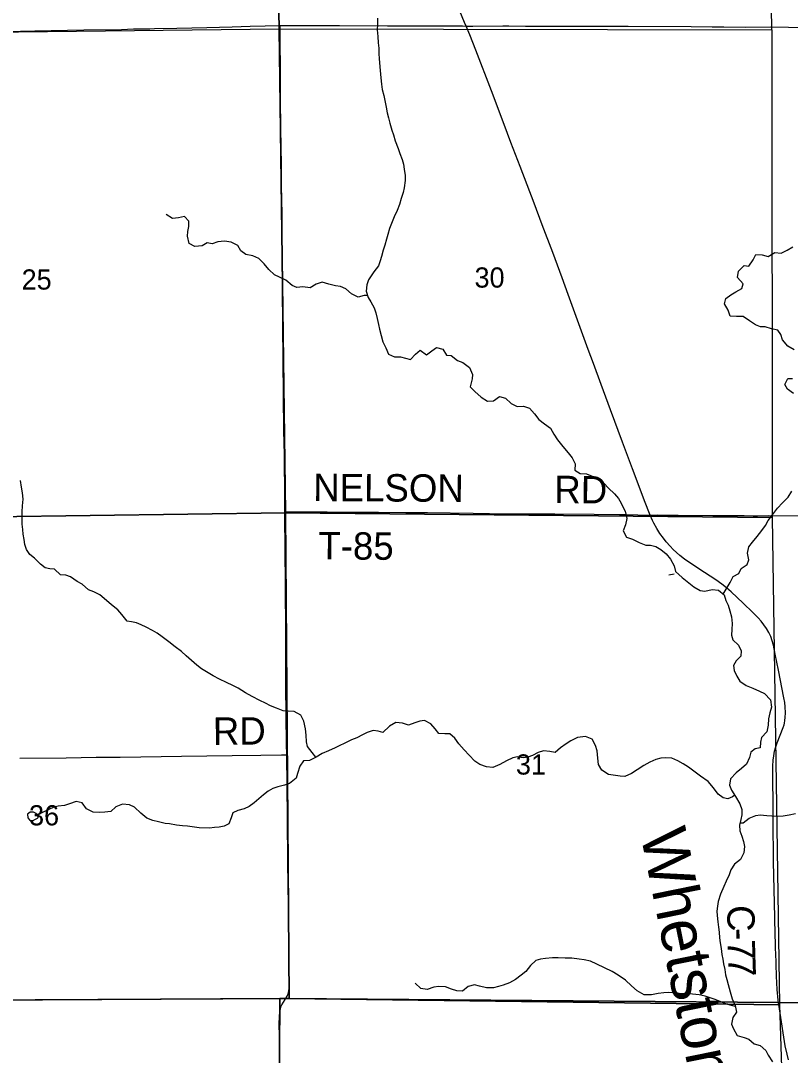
# Model space of a CAD drawing. Extents: x 0 to 70.2, y 0 to 31.4.
# Drawn here: x 4.18 to 5.776, y 18.211 to 20.357 of the extents above; entities that cross this region are included whole.
import ezdxf

# ---------------------------------------------------------------- set-up
doc = ezdxf.new("R2010")
doc.units = 0
for name, color, linetype in [('GM_X_County_Road', 7, 'Continuous'), ('GM_X_County_Road_Text', 7, 'Continuous'), ('GM_X_Minor_Lake', 7, 'Continuous'), ('GM_X_Minor_River', 7, 'Continuous'), ('GM_X_Minor_River_Text', 7, 'Continuous'), ('GM_X_Section', 7, 'Continuous'), ('GM_X_Section_Text', 7, 'Continuous'), ('GM_X_State_Route', 7, 'Continuous'), ('GM_X_Township_Road', 7, 'Continuous'), ('GM_X_Township_Road_Text', 7, 'Continuous')]:
    doc.layers.add(name, color=color, linetype=linetype)

msp = doc.modelspace()

# ---------------------------------------------------------------- linework, layer by layer
at = {"layer": 'GM_X_County_Road'}
for points in [[(5.1036, 20.3455), (5.1003, 20.3533), (5.0907, 20.3762), (5.0746, 20.4168), (5.0732, 20.4206), (5.0703, 20.4283), (5.054, 20.4719), (5.0374, 20.5145), (5.0298, 20.5347), (5.0262, 20.5443)], [(3.6924, 20.3283), (3.7175, 20.3279), (3.7548, 20.3276), (3.7734, 20.3275), (3.8387, 20.3284), (3.9101, 20.3298), (3.9352, 20.3303), (4.0435, 20.3325), (4.1495, 20.3344), (4.209, 20.3357), (4.3109, 20.3376), (4.3888, 20.3388), (4.4136, 20.3397), (4.4478, 20.3401), (4.4571, 20.3406), (4.5037, 20.3416), (4.5658, 20.3429), (4.6186, 20.3442), (4.6559, 20.3455), (4.7179, 20.3465)], [(4.7179, 20.3465), (4.7443, 20.3469), (4.782, 20.3471), (4.8413, 20.3471), (4.9408, 20.346), (5.0429, 20.3458), (5.0742, 20.346), (5.0964, 20.346), (5.1036, 20.3455)], [(5.1036, 20.3455), (5.1179, 20.3452), (5.1801, 20.3461), (5.1925, 20.3459), (5.2267, 20.3457), (5.3195, 20.3451), (5.3748, 20.3452), (5.4401, 20.3451), (5.5706, 20.3444), (5.6141, 20.3443), (5.637, 20.3441), (5.638, 20.3441)], [(5.4857, 19.3314), (5.4844, 19.3344), (5.4753, 19.3575), (5.4488, 19.4271), (5.4281, 19.4824), (5.4031, 19.5494), (5.3839, 19.6019), (5.3677, 19.6455), (5.3571, 19.6747), (5.3157, 19.7886), (5.3027, 19.8235), (5.2833, 19.8759), (5.2616, 19.9337), (5.2446, 19.9783), (5.2156, 20.0547), (5.1967, 20.1041), (5.1823, 20.1418), (5.1561, 20.2116), (5.1241, 20.2959), (5.1114, 20.3276), (5.1036, 20.3455)], [(5.638, 20.3441), (5.6825, 20.3436), (5.7353, 20.3437), (5.7726, 20.3433), (5.8783, 20.343), (5.9498, 20.3425), (5.9848, 20.3424)], [(5.7519, 18.3199), (5.7512, 18.3256), (5.7489, 18.3471), (5.7473, 18.375), (5.746, 18.4246), (5.7457, 18.4291), (5.7458, 18.4326), (5.7446, 18.4716), (5.744, 18.4848), (5.7439, 18.4941), (5.7442, 18.4973), (5.7415, 18.6123), (5.7411, 18.6433), (5.7409, 18.6682), (5.7406, 18.7241), (5.7397, 18.7924), (5.7399, 18.8109), (5.7407, 18.8233), (5.7418, 18.8324), (5.7435, 18.8415), (5.7459, 18.8504), (5.749, 18.8592), (5.7613, 18.8905), (5.7633, 18.8964), (5.764, 18.8995), (5.7651, 18.9056), (5.7658, 18.9118), (5.7662, 18.9212), (5.7657, 18.9337), (5.7646, 18.943), (5.763, 18.9522), (5.7514, 19.0097), (5.745, 19.0432), (5.7412, 19.0615), (5.7388, 19.0706), (5.7355, 19.0794), (5.7315, 19.0879), (5.7268, 19.096), (5.7214, 19.1038), (5.7156, 19.1111), (5.7094, 19.1181), (5.6984, 19.1291), (5.6783, 19.1486), (5.6534, 19.172), (5.644, 19.1802), (5.6342, 19.188), (5.6215, 19.197), (5.5981, 19.2123), (5.5722, 19.2294), (5.5569, 19.24), (5.547, 19.2475), (5.5399, 19.2535), (5.5332, 19.2598), (5.5268, 19.2666), (5.5187, 19.2759), (5.5129, 19.2833), (5.5058, 19.2934), (5.4992, 19.3038), (5.4932, 19.3146), (5.4905, 19.3202), (5.4857, 19.3314)], [(5.7724, 18.2014), (5.7694, 18.2133), (5.7657, 18.2306), (5.7536, 18.3071), (5.7519, 18.3199)]]:
    msp.add_lwpolyline(points, dxfattribs=at)
at = {"layer": 'GM_X_Minor_Lake'}
for points in [[(4.2147, 18.7092), (4.212, 18.7126), (4.206, 18.7149), (4.1995, 18.715), (4.1934, 18.7112), (4.1942, 18.7036), (4.1976, 18.699), (4.2021, 18.6963), (4.2044, 18.6971), (4.2105, 18.7005)], [(4.2105, 18.7005), (4.2145, 18.7028), (4.2158, 18.7041), (4.2158, 18.7052), (4.2147, 18.7092)]]:
    msp.add_lwpolyline(points, dxfattribs=at)
at = {"layer": 'GM_X_Minor_River'}
for points in [[(4.9201, 20.3617), (4.9196, 20.3492), (4.9192, 20.3378), (4.9203, 20.3238), (4.9213, 20.3109), (4.9228, 20.2995), (4.9227, 20.2885), (4.9231, 20.2778), (4.9252, 20.2535), (4.9267, 20.2383), (4.9281, 20.2254), (4.9296, 20.214), (4.9329, 20.2015), (4.9348, 20.1912), (4.9381, 20.1772), (4.94, 20.1658), (4.9426, 20.1555), (4.9452, 20.1445), (4.9493, 20.1297), (4.953, 20.1198), (4.9568, 20.1076), (4.9628, 20.0917), (4.9661, 20.081), (4.971, 20.0692), (4.9736, 20.059), (4.9755, 20.0491), (4.9769, 20.0358), (4.9772, 20.0252), (4.9753, 20.0104), (4.973, 20.0005), (4.9691, 19.9877), (4.9656, 19.9759), (4.9606, 19.9634), (4.9541, 19.9502), (4.9487, 19.9361), (4.9449, 19.9255), (4.941, 19.9134), (4.9387, 19.9035), (4.9349, 19.891), (4.9318, 19.8808), (4.9279, 19.8679), (4.9252, 19.8584), (4.9218, 19.8486), (4.9122, 19.8357), (4.9015, 19.8191), (4.8977, 19.8089), (4.8965, 19.796), (4.9002, 19.783), (4.9058, 19.7735), (4.9126, 19.7613), (4.9163, 19.7511), (4.9193, 19.7393), (4.9219, 19.7264), (4.9242, 19.7169), (4.9275, 19.7036), (4.9312, 19.691), (4.9372, 19.6781), (4.9429, 19.6652), (4.9554, 19.6594), (4.9675, 19.6597), (4.9781, 19.657)], [(4.8991, 19.7867), (4.8922, 19.7865), (4.8797, 19.7831), (4.8661, 19.7904), (4.854, 19.8007), (4.8434, 19.8053), (4.8324, 19.8069), (4.8187, 19.81), (4.8047, 19.8146), (4.7926, 19.8101), (4.78, 19.8026), (4.7652, 19.805), (4.7527, 19.8031), (4.7428, 19.8073), (4.7296, 19.8184), (4.7167, 19.8249), (4.7061, 19.8295), (4.6944, 19.841), (4.685, 19.8528), (4.674, 19.8639), (4.6612, 19.8692), (4.6464, 19.872), (4.6366, 19.8796), (4.6298, 19.8903), (4.6162, 19.8975), (4.6021, 19.8995), (4.5885, 19.8984), (4.5767, 19.8939), (4.5664, 19.8959), (4.5558, 19.8899), (4.541, 19.8884), (4.5293, 19.8945), (4.5255, 19.9101), (4.5263, 19.9196), (4.5283, 19.9302), (4.5283, 19.9409), (4.5197, 19.9508), (4.5067, 19.9478), (4.4946, 19.9467), (4.4817, 19.9551)], [(5.7842, 19.674), (5.7713, 19.6816), (5.76, 19.6946), (5.7566, 19.7056), (5.7506, 19.7151), (5.7373, 19.7178), (5.7241, 19.7221), (5.7142, 19.7221), (5.704, 19.726), (5.6915, 19.734), (5.6786, 19.7435), (5.6646, 19.7432), (5.6517, 19.7437), (5.6472, 19.7562), (5.6397, 19.7692), (5.6428, 19.7809), (5.653, 19.7881), (5.6629, 19.7945), (5.6755, 19.8013), (5.6786, 19.8107), (5.6669, 19.8244), (5.6685, 19.8373), (5.6807, 19.8491), (5.6901, 19.8479), (5.6993, 19.8607), (5.705, 19.8717), (5.7176, 19.8713), (5.7301, 19.8674), (5.7442, 19.8761), (5.757, 19.8749), (5.7696, 19.8809), (5.7814, 19.8877)], [(4.9781, 19.657), (4.9884, 19.6543), (4.9987, 19.6649), (5.0082, 19.6732), (5.0218, 19.6636), (5.0328, 19.6723), (5.0424, 19.6787), (5.0552, 19.6752), (5.0632, 19.6634), (5.0726, 19.6623), (5.0855, 19.6523), (5.0968, 19.6481), (5.1105, 19.6374), (5.1168, 19.6233), (5.116, 19.6138), (5.1118, 19.5975), (5.122, 19.5876), (5.1348, 19.5762), (5.1477, 19.5674), (5.1606, 19.5681), (5.1732, 19.5775), (5.1857, 19.574), (5.1974, 19.5626), (5.2095, 19.5568), (5.2224, 19.5571), (5.2353, 19.5533), (5.2455, 19.5415), (5.2545, 19.5293), (5.2666, 19.5209), (5.2787, 19.5117), (5.2859, 19.4991), (5.293, 19.4873), (5.3043, 19.4736), (5.3153, 19.4607), (5.3239, 19.4504), (5.33, 19.4374), (5.3295, 19.4245), (5.3405, 19.4173), (5.3534, 19.4168), (5.3655, 19.4122), (5.3757, 19.4072), (5.3893, 19.3973), (5.3992, 19.3874), (5.4112, 19.3755), (5.4199, 19.3656), (5.4227, 19.3611)], [(5.783, 19.5836), (5.7705, 19.5928), (5.7648, 19.6023), (5.771, 19.6144), (5.7805, 19.6144)], [(4.7921, 18.8292), (4.7841, 18.8393), (4.7747, 18.8511), (4.7728, 18.8613), (4.7717, 18.875), (4.7707, 18.8879), (4.7673, 18.9042), (4.7609, 18.9164), (4.7473, 18.9237), (4.7344, 18.9249), (4.7238, 18.9257), (4.7102, 18.9307), (4.6977, 18.9361), (4.6878, 18.9415), (4.6757, 18.9468), (4.6598, 18.9549), (4.6458, 18.9625), (4.6307, 18.9721), (4.6197, 18.9778), (4.6068, 18.984), (4.5921, 18.9913), (4.5788, 18.9982), (4.5686, 19.0039), (4.555, 19.0127), (4.5451, 19.0203), (4.5338, 19.0299), (4.5229, 19.0394), (4.513, 19.0482), (4.4998, 19.0581), (4.4869, 19.0685), (4.4733, 19.0792), (4.4627, 19.0864), (4.4529, 19.0918), (4.4397, 19.0987), (4.4294, 19.1037), (4.4196, 19.1079), (4.4097, 19.1098), (4.4003, 19.1114), (4.3897, 19.1255), (4.3814, 19.135), (4.3682, 19.145), (4.3576, 19.1545), (4.344, 19.1659), (4.3311, 19.1721), (4.3205, 19.1763), (4.3069, 19.1878), (4.2971, 19.1935), (4.2831, 19.2031), (4.2732, 19.2069), (4.2622, 19.2077), (4.2498, 19.2195), (4.2399, 19.22), (4.2304, 19.2219), (4.2206, 19.2296), (4.2085, 19.2418), (4.1987, 19.2494), (4.1915, 19.2597), (4.1885, 19.2703), (4.1867, 19.281), (4.1848, 19.292), (4.1838, 19.3015), (4.183, 19.3125), (4.1827, 19.3239), (4.1824, 19.3379), (4.1832, 19.3508), (4.1848, 19.3645), (4.1837, 19.3774), (4.1815, 19.3892), (4.1793, 19.4032)], [(5.6368, 19.1676), (5.6452, 19.1812), (5.6513, 19.1914), (5.6578, 19.2039), (5.6696, 19.2103), (5.6742, 19.2205), (5.6868, 19.2288), (5.6902, 19.2387), (5.6873, 19.2524), (5.6904, 19.2652), (5.6976, 19.2755), (5.7075, 19.2868), (5.7175, 19.2993), (5.7247, 19.3099), (5.7305, 19.3205), (5.7412, 19.3348), (5.7496, 19.3454), (5.7602, 19.3568), (5.7717, 19.3689), (5.7793, 19.3813)], [(5.4227, 19.3611), (5.4335, 19.3398), (5.4372, 19.3242), (5.4341, 19.3113), (5.4295, 19.2984), (5.4362, 19.2858), (5.4491, 19.2816), (5.4624, 19.2743), (5.4764, 19.269), (5.4862, 19.2689), (5.4976, 19.2662), (5.5074, 19.2601), (5.5184, 19.2513), (5.5275, 19.2402), (5.535, 19.2258), (5.538, 19.2144), (5.5516, 19.2022), (5.5621, 19.1938), (5.5761, 19.1827), (5.5894, 19.175), (5.5989, 19.1738), (5.614, 19.1772), (5.6273, 19.1756), (5.6387, 19.1661), (5.6428, 19.1543), (5.6473, 19.1444), (5.651, 19.133), (5.6544, 19.1204), (5.6558, 19.1064), (5.655, 19.0939), (5.6542, 19.0825), (5.6568, 19.0726), (5.6689, 19.0619), (5.6745, 19.0497), (5.6733, 19.0387), (5.6642, 19.0289), (5.6581, 19.0191), (5.6599, 19.0092), (5.6655, 18.9974), (5.6712, 18.9871), (5.6848, 18.9776), (5.6988, 18.9722), (5.7125, 18.966), (5.7227, 18.9611), (5.7348, 18.9481), (5.7373, 18.9329), (5.7339, 18.9215), (5.7311, 18.9086), (5.7303, 18.8957), (5.7272, 18.8817), (5.7165, 18.87), (5.7142, 18.8601), (5.7138, 18.8487), (5.7035, 18.8465), (5.694, 18.8397), (5.6913, 18.8284), (5.6852, 18.8151), (5.6753, 18.806), (5.6642, 18.7966), (5.652, 18.7841), (5.65, 18.7712), (5.6545, 18.7606), (5.6625, 18.748), (5.6715, 18.7328), (5.676, 18.721), (5.6756, 18.71), (5.6736, 18.6998), (5.6709, 18.6884), (5.6716, 18.6766), (5.6757, 18.6656), (5.6791, 18.6542), (5.6809, 18.6439), (5.6801, 18.6306), (5.6732, 18.617), (5.6606, 18.6072), (5.653, 18.5955), (5.6492, 18.5852), (5.6434, 18.572), (5.638, 18.5614), (5.6311, 18.5451), (5.6265, 18.5299), (5.6249, 18.5205), (5.6241, 18.5102), (5.6245, 18.5007), (5.6259, 18.4878), (5.627, 18.4764), (5.6285, 18.4665), (5.6295, 18.4548), (5.631, 18.4445), (5.6325, 18.4324), (5.6343, 18.4198), (5.6362, 18.4103), (5.6376, 18.4004), (5.6402, 18.389), (5.6421, 18.378), (5.6447, 18.3685), (5.6473, 18.3579), (5.6514, 18.3423), (5.6559, 18.3282), (5.6615, 18.3142), (5.6649, 18.3005)], [(5.5353, 19.2091), (5.5243, 19.2068)], [(5.661, 18.7504), (5.656, 18.7473), (5.6465, 18.7428), (5.637, 18.7447), (5.6268, 18.7528), (5.617, 18.7657), (5.6057, 18.7787), (5.5902, 18.7897), (5.5762, 18.8001), (5.5652, 18.8085), (5.5539, 18.8157), (5.5429, 18.8215), (5.5304, 18.8269), (5.5171, 18.8281), (5.5076, 18.827), (5.4974, 18.8244), (5.4848, 18.8191), (5.4723, 18.812), (5.4582, 18.8029), (5.4468, 18.7954), (5.4331, 18.7894), (5.4236, 18.7902), (5.4088, 18.7922), (5.399, 18.7937), (5.385, 18.8021), (5.3782, 18.8143), (5.3767, 18.8272), (5.3757, 18.8424), (5.3723, 18.8538), (5.3652, 18.8668), (5.3511, 18.8722), (5.3348, 18.87), (5.3207, 18.8632), (5.3112, 18.8572), (5.2998, 18.8485), (5.2884, 18.8391), (5.2774, 18.841), (5.2645, 18.8426), (5.2531, 18.8392), (5.2413, 18.8328), (5.2318, 18.8295), (5.2223, 18.828), (5.2105, 18.8299), (5.2003, 18.8277), (5.1874, 18.8217), (5.1737, 18.8138), (5.1592, 18.8078), (5.1459, 18.8094), (5.1323, 18.8144), (5.1217, 18.8213), (5.11, 18.8335), (5.0998, 18.8445), (5.0889, 18.8567), (5.0806, 18.8685), (5.0696, 18.8777), (5.0594, 18.8774), (5.0468, 18.8782), (5.0397, 18.8881), (5.0306, 18.8984), (5.0174, 18.9053), (5.0075, 18.9038), (4.9976, 18.9005), (4.9839, 18.896), (4.9718, 18.8998), (4.9578, 18.9014), (4.9449, 18.8935), (4.9307, 18.8807), (4.9213, 18.883), (4.9107, 18.8849), (4.8985, 18.8808), (4.8886, 18.8759), (4.8768, 18.8695), (4.8662, 18.865), (4.851, 18.8579), (4.8414, 18.8534), (4.8319, 18.8489), (4.8179, 18.8421), (4.8053, 18.8369), (4.7924, 18.8293), (4.7787, 18.8226), (4.7665, 18.8215), (4.7585, 18.8105), (4.7539, 18.7957), (4.7512, 18.7859), (4.7375, 18.7746), (4.7272, 18.7712), (4.7128, 18.7679), (4.7025, 18.7641), (4.693, 18.7585), (4.6831, 18.7509), (4.6736, 18.743), (4.6641, 18.7347), (4.6534, 18.7272), (4.6431, 18.7223), (4.6302, 18.7189), (4.6196, 18.7137), (4.6161, 18.7034), (4.6115, 18.6909), (4.6016, 18.686), (4.5917, 18.6842), (4.5818, 18.6831)], [(4.5818, 18.6831), (4.5716, 18.682), (4.5496, 18.6829), (4.5352, 18.6848), (4.5257, 18.686), (4.5155, 18.6868), (4.5026, 18.6884), (4.4885, 18.6908), (4.4791, 18.6919), (4.4658, 18.695), (4.4537, 18.6978), (4.4416, 18.7028), (4.4291, 18.7135), (4.4155, 18.7257), (4.4056, 18.7306), (4.3905, 18.7315), (4.3768, 18.7262), (4.3669, 18.7164), (4.354, 18.715), (4.3441, 18.7146), (4.3297, 18.7155), (4.3161, 18.722), (4.307, 18.7349), (4.2945, 18.7373), (4.2808, 18.7324), (4.2706, 18.7294), (4.2576, 18.728), (4.2482, 18.7257), (4.2145, 18.7094)], [(5.672, 18.693), (5.6781, 18.6933), (5.6907, 18.7031), (5.7044, 18.7083), (5.7139, 18.7094), (5.7275, 18.7086), (5.7382, 18.7078), (5.748, 18.707), (5.7613, 18.7073), (5.7742, 18.7095), (5.7867, 18.7125)], [(5.662, 18.3122), (5.657, 18.3138), (5.6441, 18.3173), (5.6308, 18.3223), (5.6202, 18.3265), (5.61, 18.33), (5.5994, 18.3334), (5.5869, 18.3365), (5.5736, 18.3381), (5.5633, 18.3386), (5.5497, 18.3386), (5.5376, 18.3402), (5.5243, 18.341), (5.514, 18.3407), (5.5023, 18.3389), (5.4886, 18.3366), (5.473, 18.3367), (5.4586, 18.3444), (5.4466, 18.3551), (5.4341, 18.3665), (5.419, 18.3772), (5.4069, 18.3849), (5.3906, 18.3925), (5.3747, 18.4002), (5.3618, 18.406), (5.3489, 18.4091), (5.3383, 18.4106), (5.3231, 18.4122), (5.3091, 18.4127), (5.2943, 18.4131), (5.2829, 18.4128), (5.2685, 18.4117), (5.2582, 18.4103), (5.2484, 18.4077), (5.2373, 18.3975), (5.2274, 18.3846), (5.2178, 18.3771), (5.2064, 18.3684), (5.1935, 18.3612), (5.1806, 18.3564), (5.1711, 18.3538), (5.1608, 18.3508), (5.146, 18.3508), (5.1312, 18.3543), (5.121, 18.357), (5.1081, 18.3537), (5.0963, 18.3443), (5.0841, 18.3447), (5.0735, 18.3482), (5.0606, 18.3532), (5.0474, 18.354), (5.0367, 18.3521), (5.0227, 18.3477), (5.0098, 18.3492), (4.9977, 18.3603)], [(5.6649, 18.3005), (5.6568, 18.2895), (5.6541, 18.2755), (5.6586, 18.266), (5.6661, 18.2523), (5.6802, 18.2476), (5.6904, 18.2446), (5.701, 18.2346), (5.7139, 18.2315), (5.7252, 18.2208), (5.7305, 18.211), (5.7391, 18.1976)]]:
    msp.add_lwpolyline(points, dxfattribs=at)
at = {"layer": 'GM_X_Section'}
for points in [[(4.716, 20.3402), (4.7288, 19.3363), (3.7154, 19.3219), (3.6935, 20.3278)], [(5.7381, 20.3376), (5.7388, 19.3264), (4.7288, 19.3363), (4.716, 20.3402)], [(3.7154, 19.3219), (4.7288, 19.3363), (4.7368, 18.3286), (4.7171, 18.3286), (3.7317, 18.3233)], [(4.7288, 19.3363), (5.7388, 19.3264), (5.7536, 18.3157), (4.7368, 18.3286)], [(4.7171, 18.3286), (4.7109, 17.3315), (3.7116, 17.3342), (3.715, 18.323), (3.7317, 18.3233)], [(4.7171, 18.3286), (4.7368, 18.3286), (5.7536, 18.3157), (5.7675, 17.8852), (5.7641, 17.3372), (4.7109, 17.3315)]]:
    msp.add_lwpolyline(points, close=True, dxfattribs=at)
at = {"layer": 'GM_X_Section_Text'}
for points in [[(6.7461, 18.306), (5.7517, 18.3204), (4.729, 18.3286), (3.8196, 18.3236)], [(3.8196, 18.3236), (4.729, 18.3286), (5.7517, 18.3204), (6.7461, 18.306)]]:
    msp.add_lwpolyline(points, dxfattribs=at)
at = {"layer": 'GM_X_State_Route'}
for points in [[(4.7047, 20.9), (3.6817, 20.9), (3.6935, 20.3278), (4.716, 20.3402)], [(5.7295, 20.9), (4.7047, 20.9), (4.716, 20.3402), (5.7381, 20.3376)]]:
    msp.add_lwpolyline(points, close=True, dxfattribs=at)
at = {"layer": 'GM_X_Township_Road'}
for points in [[(4.7276, 19.3383), (4.7274, 19.3505), (4.7275, 19.394), (4.7271, 19.4282), (4.7268, 19.4562), (4.7258, 19.5059), (4.7223, 19.8729), (4.7222, 19.9269), (4.7218, 19.9581), (4.7216, 19.9829), (4.7209, 20.0171), (4.7205, 20.0572), (4.7195, 20.1335), (4.7186, 20.1954), (4.7185, 20.2357), (4.7179, 20.3343), (4.7179, 20.3465)], [(4.7276, 19.3383), (4.8154, 19.338), (4.8654, 19.3377), (4.8928, 19.3376), (4.922, 19.3373), (4.9785, 19.3369), (5.0239, 19.3366), (5.1181, 19.3354), (5.1867, 19.3343), (5.2384, 19.3339), (5.2878, 19.3337), (5.3694, 19.3332), (5.4218, 19.3329), (5.4346, 19.3327), (5.4857, 19.3314)], [(4.7314, 18.8343), (4.7311, 18.8564), (4.7307, 18.9155), (4.7299, 18.9776), (4.7299, 19.0458), (4.7297, 19.0925), (4.7286, 19.2666), (4.7277, 19.3226), (4.7276, 19.3383)], [(5.4857, 19.3314), (5.5015, 19.3316), (5.5202, 19.3314), (5.5433, 19.3312)], [(5.5433, 19.3312), (5.6157, 19.3306), (5.6249, 19.3305), (5.6434, 19.3305), (5.6496, 19.3304), (5.6713, 19.3303), (5.6806, 19.3302), (5.6992, 19.3301), (5.7085, 19.3301), (5.7302, 19.3305), (5.8416, 19.3301), (5.8695, 19.33), (5.9037, 19.3295), (5.9277, 19.3291)], [(4.1779, 18.8271), (4.2741, 18.8282), (4.3361, 18.829), (4.3858, 18.8294), (4.4292, 18.8301), (4.513, 18.8313), (4.6185, 18.8328), (4.6775, 18.8335), (4.7209, 18.8341), (4.7314, 18.8343)], [(4.7346, 18.3385), (4.7354, 18.3412), (4.7365, 18.3488), (4.7365, 18.3563), (4.7366, 18.3716), (4.7361, 18.3934), (4.7361, 18.4431), (4.7349, 18.5208), (4.734, 18.6109), (4.7329, 18.7042), (4.7314, 18.8343)], [(4.716, 17.8372), (4.7157, 17.8562), (4.7161, 17.9184), (4.7161, 17.9619), (4.7166, 18.0209), (4.7165, 18.226), (4.7164, 18.2509), (4.7161, 18.2758), (4.7164, 18.2914), (4.7171, 18.3007), (4.7176, 18.3039), (4.7183, 18.307), (4.7192, 18.31), (4.7203, 18.313), (4.7217, 18.3158), (4.7249, 18.3212), (4.7282, 18.3264), (4.7292, 18.3281)], [(4.7292, 18.3281), (4.7323, 18.3334), (4.734, 18.3368), (4.7346, 18.3385)]]:
    msp.add_lwpolyline(points, dxfattribs=at)

# ---------------------------------------------------------------- texts
at = {"layer": 'GM_X_County_Road_Text'}
for s, rotation, p in [('C', 269.516, (5.6458, 18.5227)), ('-', 271.2886, (5.6454, 18.4741)), ('7', 271.7162, (5.646, 18.4504)), ('7', 271.8933, (5.647, 18.4152))]:
    msp.add_text(s, height=0.0568, rotation=rotation, dxfattribs=at).set_placement(p)
at = {"layer": 'GM_X_Minor_River_Text'}
msp.add_text('Whetstone', height=0.09474, rotation=281.4771, dxfattribs=at).set_placement((5.4648, 18.6713))
at = {"layer": 'GM_X_Section_Text'}
for s, p in [('25', (4.1816, 19.7991)), ('30', (5.1212, 19.8032)), ('31', (5.207, 18.7932)), ('36', (4.197, 18.6878))]:
    msp.add_text(s, height=0.04186, rotation=0, dxfattribs=at).set_placement(p)
at = {"layer": 'GM_X_Township_Road_Text'}
for s, rotation, p in [('NELSON', 359.6537, (4.7863, 19.3605)), ('RD', 359.5045, (5.2864, 19.3563)), ('T-85', 359.6471, (4.797, 19.2395)), ('RD', 0.4937, (4.5785, 18.8547))]:
    msp.add_text(s, height=0.05682, rotation=rotation, dxfattribs=at).set_placement(p)

doc.saveas('drawing.dxf')
